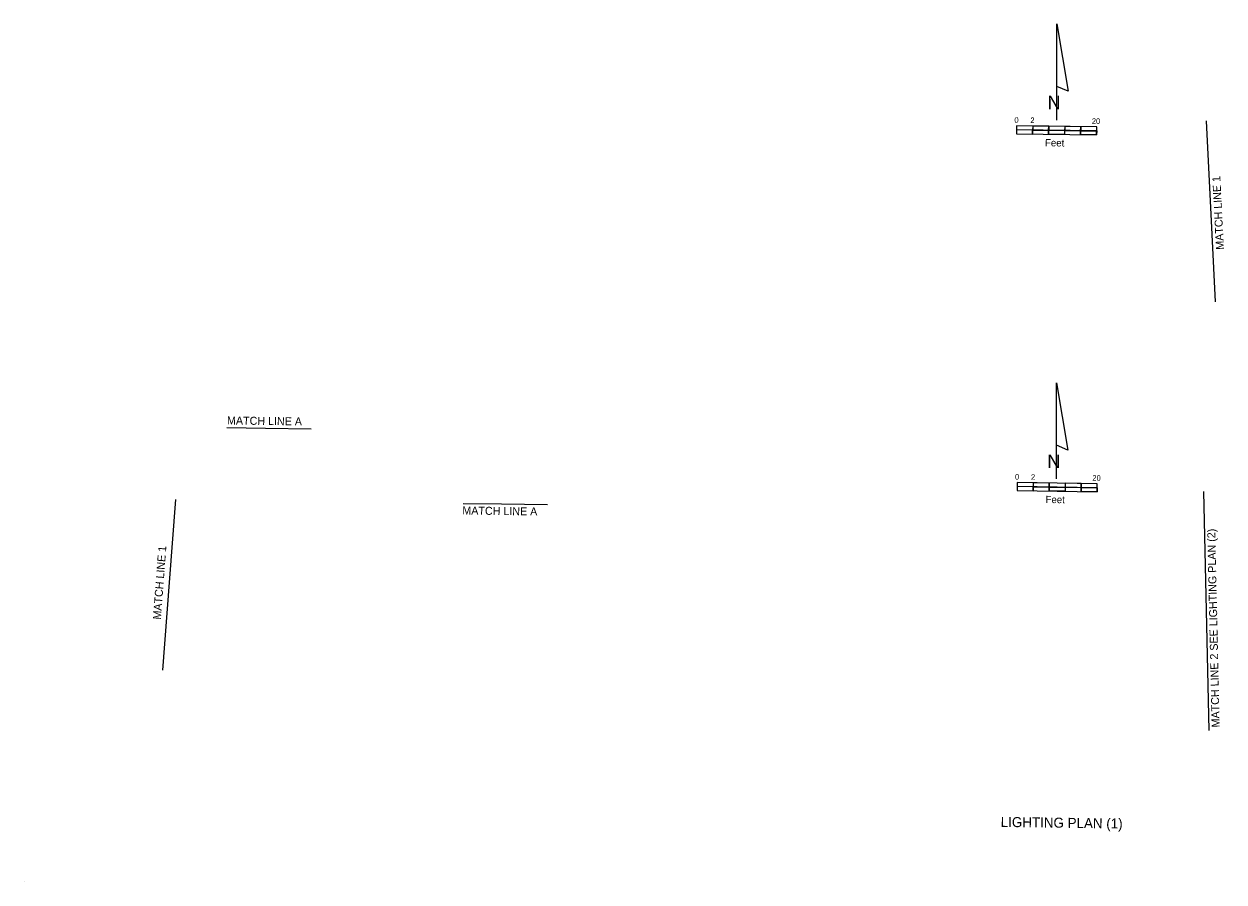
# Model space of a CAD drawing. Extents: x 927153 to 927453, y 636524 to 636738.
import ezdxf

# ---------------------------------------------------------------- set-up
doc = ezdxf.new("R2010")
doc.units = 0
for name, color, linetype in [('AdhocPoint_dp', 7, 'Continuous'), ('MatchLines_dp', 7, 'Continuous'), ('NorthArw_dp', 7, 'Continuous'), ('Scale_dp', 7, 'Continuous'), ('TextMisc', 7, 'Continuous')]:
    doc.layers.add(name, color=color, linetype=linetype)

msp = doc.modelspace()

# ---------------------------------------------------------------- linework, layer by layer
at = {"layer": 'AdhocPoint_dp'}
msp.add_line((927152.85, 636524.17), (927152.85, 636524.17), dxfattribs=at)
at = {"layer": 'MatchLines_dp'}
for points in [[(927450.59, 636669.04), (927449.73, 636685.94), (927448.28, 636714.29)], [(927203.55, 636637.66), (927213.18, 636637.53), (927224.61, 636637.37)], [(927448.98, 636561.97), (927448.31, 636591.96), (927447.64, 636621.69)], [(927187.55, 636577.07), (927189.19, 636599.01), (927190.75, 636619.72)], [(927262.55, 636618.72), (927272.18, 636618.59), (927283.61, 636618.43)]]:
    msp.add_lwpolyline(points, dxfattribs=at)
at = {"layer": 'NorthArw_dp'}
for p, q in [((927410.87, 636714.48), (927410.87, 636738.48)), ((927410.81, 636624.84), (927410.81, 636648.84))]:
    msp.add_line(p, q, dxfattribs=at)
for points in [[(927410.87, 636722.88), (927410.87, 636738.48), (927413.75, 636721.68)], [(927410.81, 636633.24), (927410.81, 636648.84), (927413.69, 636632.04)]]:
    msp.add_lwpolyline(points, close=True, dxfattribs=at)
at = {"layer": 'Scale_dp'}
for p, q in [((927400.87, 636713.04), (927400.85, 636711.04)), ((927420.87, 636712.76), (927400.87, 636713.04)), ((927404.87, 636712.98), (927404.85, 636710.98)), ((927408.87, 636712.93), (927408.85, 636710.93)), ((927412.87, 636712.87), (927412.85, 636710.87)), ((927416.87, 636712.82), (927416.85, 636710.82)), ((927400.85, 636711.04), (927420.85, 636710.76)), ((927420.86, 636711.76), (927400.86, 636712.04)), ((927420.85, 636710.76), (927420.87, 636712.76)), ((927401.01, 636623.93), (927400.99, 636621.93)), ((927421, 636622.65), (927401, 636622.93)), ((927421.01, 636623.65), (927401.01, 636623.93)), ((927405.01, 636623.87), (927404.99, 636621.87)), ((927409.01, 636623.82), (927408.99, 636621.82)), ((927413.01, 636623.76), (927412.99, 636621.76)), ((927417.01, 636623.71), (927416.98, 636621.71)), ((927420.98, 636621.65), (927421.01, 636623.65)), ((927400.99, 636621.93), (927420.98, 636621.65))]:
    msp.add_line(p, q, dxfattribs=at)
for points in [[(927404.86, 636711.98), (927408.86, 636711.93), (927408.87, 636712.93), (927404.87, 636712.98)], [(927412.86, 636711.87), (927416.86, 636711.82), (927416.87, 636712.82), (927412.87, 636712.87)], [(927400.85, 636711.04), (927404.85, 636710.98), (927404.86, 636711.98), (927400.86, 636712.04)], [(927408.86, 636711.93), (927412.86, 636711.87), (927412.85, 636710.87), (927408.85, 636710.93)], [(927416.86, 636711.82), (927420.86, 636711.76), (927420.85, 636710.76), (927416.85, 636710.82)], [(927400.99, 636621.93), (927404.99, 636621.87), (927405, 636622.87), (927401, 636622.93)], [(927405, 636622.87), (927409, 636622.82), (927409.01, 636623.82), (927405.01, 636623.87)], [(927413, 636622.76), (927417, 636622.71), (927417.01, 636623.71), (927413.01, 636623.76)], [(927409, 636622.82), (927413, 636622.76), (927412.99, 636621.76), (927408.99, 636621.82)], [(927417, 636622.71), (927421, 636622.65), (927420.98, 636621.65), (927416.98, 636621.71)]]:
    msp.add_lwpolyline(points, close=True, dxfattribs=at)

# ---------------------------------------------------------------- texts
at = {"layer": 'MatchLines_dp'}
for s, rotation, p in [('MATCH LINE 1', 92.9286, (927452.68, 636682.15)), ('MATCH LINE A', 359.2043, (927203.56, 636638.46)), ('MATCH LINE A', 359.2043, (927262.36, 636615.97)), ('MATCH LINE 2 SEE LIGHTING PLAN (2)', 91.2824, (927451.59, 636562.8)), ('MATCH LINE 1', 85.7184, (927187.05, 636589.67))]:
    msp.add_text(s, height=2, rotation=rotation, dxfattribs=at).set_placement(p)
at = {"layer": 'NorthArw_dp'}
for p in [(927408.59, 636717.19), (927408.53, 636627.55)]:
    msp.add_text('N', height=3.36, dxfattribs=at).set_placement(p)
at = {"layer": 'Scale_dp'}
for s, height, p in [('0', 1.4, (927400.3, 636713.8)), ('2', 1.4, (927404.29, 636713.74)), ('20', 1.4, (927419.64, 636713.53)), ('Feet', 1.8, (927407.94, 636707.94)), ('0', 1.4, (927400.44, 636624.69)), ('2', 1.4, (927404.43, 636624.63)), ('20', 1.4, (927419.78, 636624.42)), ('Feet', 1.8, (927408.08, 636618.83))]:
    msp.add_text(s, height=height, rotation=359.2043, dxfattribs=at).set_placement(p)
at = {"layer": 'TextMisc'}
msp.add_text('      LIGHTING PLAN (1)        ', height=2.5, rotation=359.2043, dxfattribs=at).set_placement((927391.3, 636538.01))

doc.saveas('drawing.dxf')
